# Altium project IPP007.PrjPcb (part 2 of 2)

## Sheet IPP007_SupportTop.SchDoc
size 431 x 279 mm; Date: Not shown in title block; ApprovedBy: Not shown in title block; CheckedBy: Not shown in title block; Author: Not shown in title block; CompanyName: Not shown in title block; Engineer: Not shown in title block; Organization: Not shown in title block; Address1: Not shown in title block; Address2: Not shown in title block; Address3: Not shown in title block; Address4: Not shown in title block; DocumentNumber: 10; Revision: Use project parameter SCH_Rev; SheetNumber: 10; SheetTotal: 14; PageSetup: Record=PageOptions¦CenterHorizontal=True¦CenterVertical=True¦PrintScale=1.00¦XCorrection=1.00¦YCorrection=1.00¦PrintKind=0¦BorderSize=5000000¦LeftOffset=0¦BottomOffset=0¦Orientation=2¦PaperLength=1000¦PaperWidth=1000¦Scale=100¦PaperSource=15¦PrintQuality=600¦MediaType=1¦DitherType=10¦PaperKind=Letter¦PrintScaleMode=1
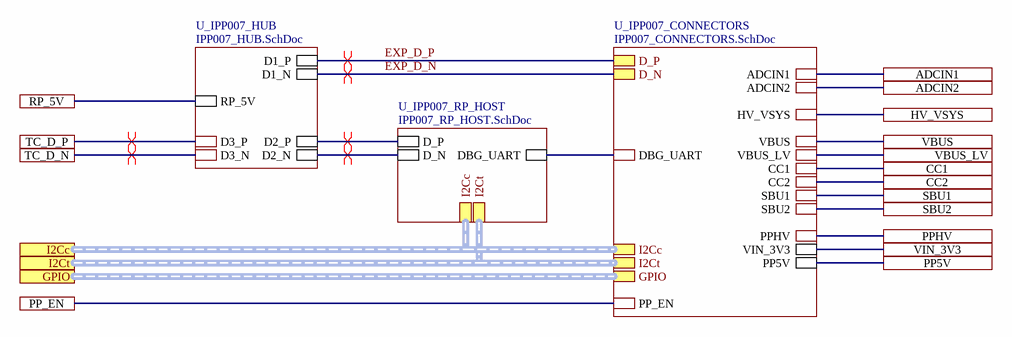
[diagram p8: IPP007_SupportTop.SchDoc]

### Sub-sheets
U_IPP007_CONNECTORS = IPP007_CONNECTORS.SchDoc: CC1, CC2, ADCIN1, ADCIN2, HV_VSYS, PPHV, PP5V, VIN_3V3, D_P, D_N, VBUS, VBUS_LV, DBG_UART, PP_EN, SBU2, SBU1, I2Cc (harness I2C), I2Ct (harness I2C), GPIO (harness GPIO)
U_IPP007_HUB = IPP007_HUB.SchDoc: D1_P, D1_N, D2_P, D2_N, RP_5V, D3_P, D3_N
U_IPP007_RP_HOST = IPP007_RP_HOST.SchDoc: DBG_UART, D_P, D_N, I2Cc (harness I2C), I2Ct (harness I2C)

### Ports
ADCIN1, ADCIN2, CC1, CC2, GPIO (harness GPIO), HV_VSYS, I2Cc (harness I2C), I2Ct (harness I2C), PP5V, PP_EN, PPHV, RP_5V, SBU1, SBU2, TC_D_N, TC_D_P, VBUS, VBUS_LV, VIN_3V3

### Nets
ADCIN1: port ADCIN1, sheet U_IPP007_CONNECTORS/ADCIN1
ADCIN2: port ADCIN2, sheet U_IPP007_CONNECTORS/ADCIN2
CC1: port CC1, sheet U_IPP007_CONNECTORS/CC1
CC2: port CC2, sheet U_IPP007_CONNECTORS/CC2
D2_N: sheet U_IPP007_RP_HOST/D_N, sheet U_IPP007_HUB/D2_N
D2_P: sheet U_IPP007_RP_HOST/D_P, sheet U_IPP007_HUB/D2_P
D3_N: port TC_D_N, sheet U_IPP007_HUB/D3_N
D3_P: port TC_D_P, sheet U_IPP007_HUB/D3_P
DBG_UART: sheet U_IPP007_CONNECTORS/DBG_UART, sheet U_IPP007_RP_HOST/DBG_UART
EXP_D_N: sheet U_IPP007_CONNECTORS/D_N, sheet U_IPP007_HUB/D1_N
EXP_D_P: sheet U_IPP007_CONNECTORS/D_P, sheet U_IPP007_HUB/D1_P
HV_VSYS: port HV_VSYS, sheet U_IPP007_CONNECTORS/HV_VSYS
PP5V: port PP5V, sheet U_IPP007_CONNECTORS/PP5V
PP_EN: port PP_EN, sheet U_IPP007_CONNECTORS/PP_EN
PPHV: port PPHV, sheet U_IPP007_CONNECTORS/PPHV
RP_5V: port RP_5V, sheet U_IPP007_HUB/RP_5V
SBU1: port SBU1, sheet U_IPP007_CONNECTORS/SBU1
SBU2: port SBU2, sheet U_IPP007_CONNECTORS/SBU2
VBUS: port VBUS, sheet U_IPP007_CONNECTORS/VBUS
VBUS_LV: port VBUS_LV, sheet U_IPP007_CONNECTORS/VBUS_LV
VIN_3V3: port VIN_3V3, sheet U_IPP007_CONNECTORS/VIN_3V3

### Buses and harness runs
harness port GPIO = sheet U_IPP007_CONNECTORS/GPIO
harness port I2Cc = sheet U_IPP007_CONNECTORS/I2Cc = sheet U_IPP007_RP_HOST/I2Cc
harness port I2Ct = sheet U_IPP007_CONNECTORS/I2Ct = sheet U_IPP007_RP_HOST/I2Ct

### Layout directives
differential pair: D2_N, D2_P, D3_N, D3_P, EXP_D_N, EXP_D_P

## Sheet IPP007_CONNECTORS.SchDoc
size 558 x 431 mm; Date: Not shown in title block; ApprovedBy: Not shown in title block; CheckedBy: Not shown in title block; Author: Not shown in title block; CompanyName: Not shown in title block; Engineer: Not shown in title block; Organization: Not shown in title block; Address1: Not shown in title block; Address2: Not shown in title block; Address3: Not shown in title block; Address4: Not shown in title block; DocumentNumber: 11; Revision: Use project parameter SCH_Rev; SheetNumber: 11; SheetTotal: 14; PageSetup: Record=PageOptions¦CenterHorizontal=True¦CenterVertical=True¦PrintScale=1.00¦XCorrection=1.00¦YCorrection=1.00¦PrintKind=0¦BorderSize=5000000¦LeftOffset=0¦BottomOffset=0¦Orientation=2¦PaperLength=1000¦PaperWidth=1000¦Scale=100¦PaperSource=15¦PrintQuality=600¦MediaType=1¦DitherType=10¦PaperKind=Letter¦PrintScaleMode=1
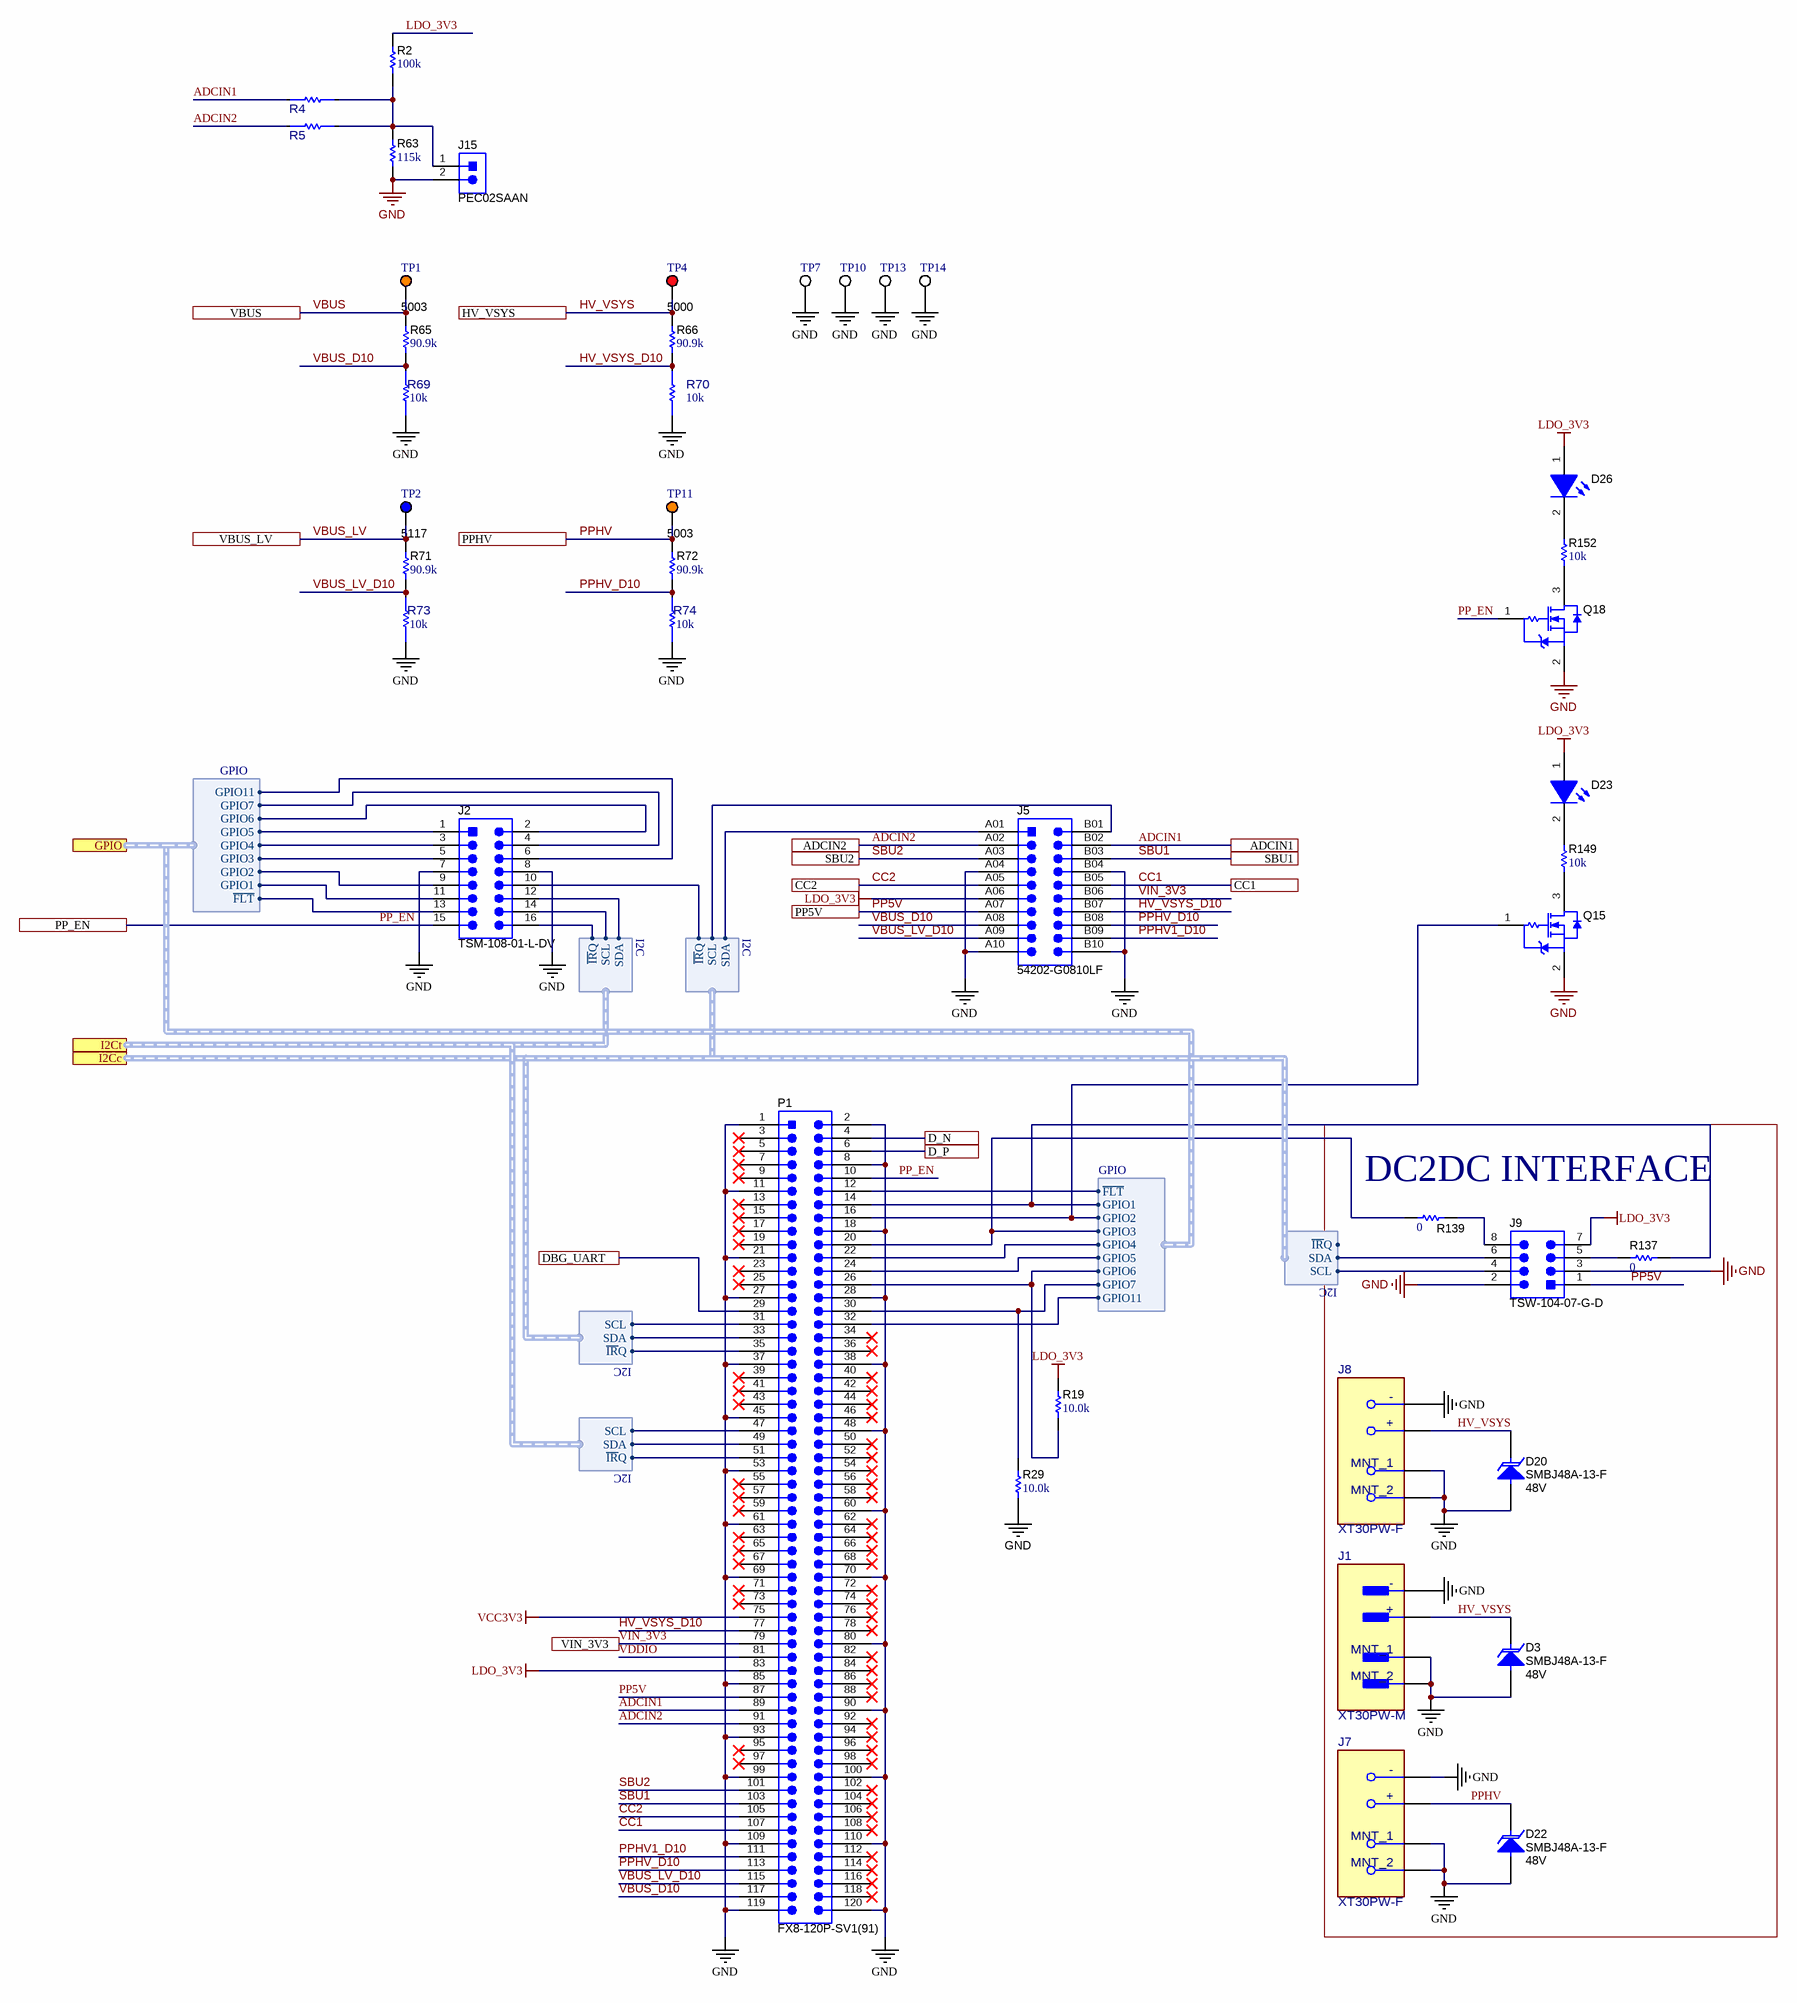
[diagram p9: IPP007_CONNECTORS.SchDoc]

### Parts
D3  SMBJ48A-13-F  value 48V  [SMB]
D20  SMBJ48A-13-F  value 48V  [SMB]
D22  SMBJ48A-13-F  value 48V  [SMB]
D23  LW QH8G-Q2S2-3K5L-1  [LW QH8G_White]  (value not drawn)
D26  LW QH8G-Q2S2-3K5L-1  [LW QH8G_White]  (value not drawn)
J1  XT30PW-M  [FP-XT30PW-M_CONN_PLUG2-MFG]
J2  TSM-108-01-L-DV  [Samtec_TSM-108-01-x-DV]
J5  54202-G0810LF  [FCI_54202-G0810LF]
J7  XT30PW-F  [FP-XT30PW-F_CONN_SOCKET_DC2-MFG]
J8  XT30PW-F  [FP-XT30PW-F_CONN_SOCKET_DC2-MFG]
J9  TSW-104-07-G-D  [TSW-104-07-G-D]
J15  PEC02SAAN  [CONN_PEC02SAAN]
P1  FX8-120P-SV1(91)  [Hirose_FX8-120P-SV1]
Q15  CSD15380F3  [YJM0003A]  (value not drawn)
Q18  CSD15380F3  [YJM0003A]  (value not drawn)
R2  ValueDisplayed: 100k  [0402L]  (hidden comment: ERJ-2RKF1003X)
R4  ERJ-H3G0R00V  [FP-ERJ-H3G0R00V_0603-MFG]  (value not drawn)
R5  ERJ-H3G0R00V  [FP-ERJ-H3G0R00V_0603-MFG]  (value not drawn)
R19  ValueDisplayed: 10.0k  [0201L]  (hidden comment: CRCW020110K0FKED)
R29  ValueDisplayed: 10.0k  [0201L]  (hidden comment: CRCW020110K0FKED)
R63  ValueDisplayed: 115k  [0402L]  (hidden comment: RC0402FR-07115KL)
R65  ValueDisplayed: 90.9k  [0402L]  (hidden comment: CRCW040290K9FKED)
R66  ValueDisplayed: 90.9k  [0402L]  (hidden comment: CRCW040290K9FKED)
R69  value 10k  [FP-CRCW040210K0FKEDC_0402-MFG]  (hidden comment: CRCW040210K0FKEDC)
R70  value 10k  [FP-CRCW040210K0FKEDC_0402-MFG]  (hidden comment: CRCW040210K0FKEDC)
R71  ValueDisplayed: 90.9k  [0402L]  (hidden comment: CRCW040290K9FKED)
R72  ValueDisplayed: 90.9k  [0402L]  (hidden comment: CRCW040290K9FKED)
R73  value 10k  [FP-CRCW040210K0FKEDC_0402-MFG]  (hidden comment: CRCW040210K0FKEDC)
R74  value 10k  [FP-CRCW040210K0FKEDC_0402-MFG]  (hidden comment: CRCW040210K0FKEDC)
R137  ValueDisplayed: 0  [0201L]  (hidden comment: CRCW02010000Z0ED)
R139  ValueDisplayed: 0  [0201L]  (hidden comment: CRCW02010000Z0ED)
R149  ValueDisplayed: 10k  [0402L]  (hidden comment: CRCW040210K0JNED)
R152  ValueDisplayed: 10k  [0402L]  (hidden comment: CRCW040210K0JNED)
TP1  5003  [Keystone5003]
TP2  5117  [Keystone5117]
TP4  5000  [Keystone5000]
TP7  5015  [Testpoint_Keystone_Miniature]  (value not drawn)
TP10  5015  [Testpoint_Keystone_Miniature]  (value not drawn)
TP11  5003  [Keystone5003]
TP13  5015  [Testpoint_Keystone_Miniature]  (value not drawn)
TP14  5015  [Testpoint_Keystone_Miniature]  (value not drawn)

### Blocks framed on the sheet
DC2DC INTERFACE: D3 D20 D22 J1 J7-J9 R137 R139

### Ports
ADCIN1, ADCIN2, CC1, CC2, D_N, D_P, DBG_UART, GPIO (harness GPIO), HV_VSYS, I2Cc (harness I2C), I2Ct (harness I2C), PP5V, PP_EN, PPHV, SBU1, SBU2, VBUS, VBUS_LV, VIN_3V3

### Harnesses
I2C: SCL, SDA, ~{IR}Q
GPIO: GPIO11, ~{FLT}, GPIO1, GPIO2, GPIO3, GPIO4, GPIO5, GPIO6, GPIO7

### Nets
GND: D3.2(A) D20.2(A) D22.2(A) J1.1(-) J1.3(MNT_1) J1.4(MNT_2) J2.7 J2.8 J5.A04 J5.A10 J5.B04 J5.B10 J7.1(-) J7.3(MNT_1) J7.4(MNT_2) J8.1(-) J8.3(MNT_1) J8.4(MNT_2) J9.2 J9.3 J15.2 P1.1 P1.2 P1.8 P1.11 P1.18 P1.21 P1.27 P1.28 P1.37 P1.38 P1.45 P1.48 P1.53 P1.60 P1.61 P1.69 P1.70 P1.80 P1.85 P1.90 P1.93 P1.99 P1.100 P1.109 P1.110 P1.119 P1.120 Q15.2(S) Q18.2(S) R29.1 R63.1 R69.1 R70.1 R73.1 R74.1 TP7.1 TP10.1 TP13.1 TP14.1
LDO_3V3: D23.1(A) D26.1(A) J5.A06 J9.7 P1.83 R2.2 R19.2
VCC3V3: P1.75
ADCIN1: J5.B02 P1.89 R4.1 ; port ADCIN1
ADCIN2: J5.A02 P1.91 R5.1 ; port ADCIN2
CC1: J5.B05 P1.107 ; port CC1
CC2: J5.A05 P1.105 ; port CC2
DBG_UART: P1.29 ; port DBG_UART
EXP_D_N: P1.4 ; port D_N
EXP_D_P: P1.6 ; port D_P
GPIO4: J2.3 P1.22 ; port GPIO.GPIO4
GPIO5: J2.1 P1.24 ; port GPIO.GPIO5
GPIO6: J2.2 P1.26 R19.1 ; port GPIO.GPIO6
GPIO7: J2.4 P1.30 R29.2 ; port GPIO.GPIO7
HV_VSYS: D3.1(K) D20.1(K) J1.2(+) J8.2(+) R66.2 TP4.1 ; port HV_VSYS
HV_VSYS_D10: J5.B07 P1.77 R66.1 R70.2
I2Cc_SCL: J5.B01 J9.4 P1.31 ; port I2Cc.SCL
I2Cc_SDA: J5.A01 J9.6 P1.33 ; port I2Cc.SDA
I2Ct_SCL: J2.14 P1.47 ; port I2Ct.SCL
I2Ct_SDA: J2.12 P1.49 ; port I2Ct.SDA
~{I2Cc_IRQ}: J2.10 P1.35 ; port I2Cc.~{IR}Q
~{I2Ct_IRQ}: J2.16 P1.51 ; port I2Ct.~{IR}Q
PP5V: J5.A07 J9.1 P1.87 ; port PP5V
PP_EN: J2.15 P1.10 Q18.1(G) ; port PP_EN
PPHV: D22.1(K) J7.2(+) R72.2 TP11.1 ; port PPHV
PPHV1_D10: J5.B09 P1.111
PPHV_D10: J5.B08 P1.113 R72.1 R74.2
SBU1: J5.B03 P1.103 ; port SBU1
SBU2: J5.A03 P1.101 ; port SBU2
VBUS: R65.2 TP1.1 ; port VBUS
VBUS_D10: J5.A08 P1.117 R65.1 R69.2
VBUS_LV: R71.2 TP2.1 ; port VBUS_LV
VBUS_LV_D10: J5.A09 P1.115 R71.1 R73.2
VDDIO: P1.81
VIN_3V3: J5.B06 P1.79 ; port VIN_3V3
NetD23_2: D23.2(K) R149.2
NetD26_2: D26.2(K) R152.2
NetJ2_5: J2.5 P1.20 R139.1 ; port GPIO.GPIO3
NetJ2_6: J2.6 P1.32 ; port GPIO.GPIO11
NetJ2_9: J2.9 P1.16 Q15.1(G) ; port GPIO.GPIO2
NetJ2_11: J2.11 P1.14 R137.1 ; port GPIO.GPIO1
NetJ2_13: J2.13 P1.12 ; port GPIO.~{FLT}
NetJ9_5: J9.5 R137.2
NetJ9_8: J9.8 R139.2
NetJ15_1: J15.1 R2.1 R4.2 R5.2 R63.2
NetQ15_3: Q15.3(D) R149.1
NetQ18_3: Q18.3(D) R152.1

Not connected (* = marked no-connect by the designer): P1 3* 5* 7* 9* 13* 15* 17* 19* 23* 25* 34* 36* 39* 40* 41* 42* 43* 44* 46* 50* 52* 54* 55* 56* 57* 58* 59* 62* 63* 64* 65* 66* 67* 68* 71* 72* 73* 74* 76* 78* 82* 84* 86* 88* 92* 94* 95* 96* 97* 98* 102* 104* 106* 108* 112* 114* 116* 118*

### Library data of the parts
D3 D20 D22 = CMP-0005570-3: Diode, TVS, Uni, 48 V, 77.4 Vc, SMB; Manufacturer: Diodes Inc.; Vbr_Min: 53.3V; AEC Category: Q101; Vbr_Max: 61.3V; Ppk: 600W; SizeZ_mm: 2.6; Ipp: 7.7A; SizeY_mm: 3.81; Vc: 77.4V; SizeAreaWB_mm2: 44.156; SizeX_mm: 5.6; SizeArea_mm2: 21.336
D23 D26 = CMP-0002919-2: LED, White, SMD; Manufacturer: OSRAM; Io_A: 5mA; Vr_V: 5V; Tjmax_C: 95°C; Value1: W; Angle: 120; Ir_A: 10nA; Vf_V: 2.8V
J1 = CMP-0121007-1: Socket, DC supply, XT30, male, PIN: 2, on PCBs, THT, yellow, 15A, 500V; Manufacturer: Amass; ContactFinish: Gold; AEC Qualified: No; Conn Orientation: Right Angle; DUT-Pitch_mm: 5mm; SizeZ_mm: 5.1mm; Standoff Height: 0.1mm
J2 = CMP-0075595-1: Header, 2.54mm, 8x2, Gold, SMT; Manufacturer: Samtec; Pitch_mm: 2.54; Gender: Male; Cert_CSA: Y; Current_A: 4.9A; Voltage_V: 475V; CT: False; Shrouded: N; Row_Count: 2; CNHeader: True
J5 = CMP-0077452-1: Header, 2.54mm, 10x2, Tin, SMT; Manufacturer: FCI; Pitch_mm: 2.54; Gender: Male; Cert_UL: Y; Voltage_V: 1.5kV; Shrouded: N; RowSpacing_mm: 5.46; Row_Count: 2
J7 J8 = CMP-0035193-3: Socket, DC supply, XT30, female, PIN: 2, on PCBs, THT, yellow, 15A; Manufacturer: Amass; ContactFinish: Gold; Voltage_V: 500V; AEC Qualified: No; Conn Orientation: Right Angle; DUT-Pitch_mm: 5mm; Is Female: yes; Standoff Height: 0.1mm
J9 = CMP-0075408-3: Header, 100mil, 4x2, Gold, TH; Manufacturer: Samtec; Gender: Male; Row_Count: 2; Cert_CSA: Y; Pitch_mm: 2.54; Green_REACh: Passed; Voltage_V: 550V; Current_A: 6.3A; Green_Lifecycle: Active; Cert_CULUS: N
J15 = CMP-0002337-1: Header, 100mil, 2x1, Tin, TH; Manufacturer: Sullins Connector Solutions; CNHeader: TRUE; Current_A: 3A; Green_Lifecycle: Not Set; Shrouded: N; Gender: Male; Green_REACh: Incomplete; Voltage_V: 1.8kV; Row_Count: 1; Pitch_mm: 2.54; CT: FALSE; Cert_UL: Y
P1 = CMP-0055794-1: Header(shrouded), 0.6mm, 60x2, Gold, SMT; Manufacturer: Hirose Electric Co. Ltd.; CNHeader: FALSE; Current_A: 400mA; Shrouded: Y; Gender: Male; Voltage_V: 100V; Row_Count: 2; Pitch_mm: 0.6
Q15 Q18 = CMP-0000206-2: MOSFET, N-CH, 20 V, 0.5 A, YJM0003A (PICOSTAR-3); Alternate Manufacturer: None; Manufacturer: Texas Instruments; SizeZ_mm: 0.35; ChType: N; Value2: 0.216 nC; Value1: 1.4; VdsMax_V: 20V; SizeX_mm: 0.69; SizeY_mm: 0.6; Vgs_V: 10V; Value: 20V; Rdson45_ohm: 1.46; SizeArea_mm2: 0.414; AEC Category: Q101; IdsMax_A: 500mA; SizeAreaWB_mm2: 2.704; U/M: EA; QgTyp_nC: 0.216
R2 = CMP-0026659-2: RES, 100 k, 1%, 0.1 W, 0402; Manufacturer: Panasonic; U/M: EA; Value2: 0.1W; EIA_Code: E96; Value: 100k; SizeArea_mm2: 0.5; TempCo: 100 ppm/C; SizeZ_mm: 0.6; AEC Category: Q200; VDC_V: 50V; Power_W: 100mW; AEC Grade: 0; SizeX_mm: 1; AEC Qualified: Yes
R4 R5 = CMP-0097467-1: 0 Ohms Jumper 0.125W, 1/8W Chip Resistor 0603 (1608 Metric) Automotive AEC-Q200 Thick Film; Manufacturer: Panasonic; Res_ohm: 0; VDC_V: 75V; Power_W: 125mW; AEC Qualified: Yes; Value: 0; SizeZ_mm: 0.55mm; AEC Grade: Grade 0
R19 R29 = CMP-0027262-3: RES, 10.0 k, 1%, 0.05 W, 0201; Manufacturer: Vishay-Dale; Power_W: 50mW; TempCo: 100 ppm/C; Value_Code: 10k0; Value: 10.0k; EIA_Code: E96; Res_ohm: 10k; SizeX_mm: 0.6; SizeY_mm: 0.3; SizeZ_mm: 0.26; Value2: 0.05W; SizeArea_mm2: 0.18; AEC Qualified: N; VDC_V: 30V; AEC Category: Q200
R63 = CMP-0077551-1: RES, 115 k, 1%, 0.063 W, 0402; Manufacturer: Yageo America; SizeArea_mm2: 0.5; AEC Qualified: N; AEC Category: Q200; Value: 115k; SizeZ_mm: 0.6; EIA_Code: E96; TempCo: 100 ppm/C; Power_W: 63mW; VDC_V: 50V; Value2: 0.063W; U/M: EA; SizeX_mm: 1.0
R65 R66 R71 R72 = CMP-0026605-2: RES, 90.9 k, 1%, 0.063 W, AEC-Q200 Grade 0, 0402; Manufacturer: Vishay-Dale; Power_W: 63mW; TempCo: 100 ppm/C; Value_Code: 90k9; Value: 90.9k; EIA_Code: E96; SizeX_mm: 1; SizeY_mm: 0.5; SizeZ_mm: 0.6; Value2: 0.063W; AEC Qualified: Y; VDC_V: 50V; AEC Category: Q200; AEC Grade: 0
R69 R70 R73 R74 = CMP-0094735-1: 10 kOhms ±1% 0.063W, 1/16W Chip Resistor 0402 (1005 Metric)  Thick Film; Manufacturer: Vishay; VDC_V: 50V; Power_W: 63mW; AEC Qualified: Yes; SizeZ_mm: 0.4mm; TempCo: 100ppm/°C; AEC Grade: Grade 0
R137 R139 = CMP-0027008-4: RES, 0, 5%, 0.05 W, 0201; Manufacturer: Vishay-Dale; Power_W: 50mW; TempCo: ppm/C; Value_Code: 0000; Value: 0; EIA_Code: E24; SizeX_mm: 0.6; SizeY_mm: 0.3; SizeZ_mm: 0.26; Value2: 0.05W; SizeArea_mm2: 0.18; AEC Qualified: N; AEC Category: Q200
R149 R152 = CMP-0026825-5: RES, 10 k, 5%, 0.063 W, AEC-Q200 Grade 0, 0402; Manufacturer: Vishay-Dale; Power_W: 63mW; TempCo: 200 ppm/C; Value_Code: 10k0; Value: 10k; EIA_Code: E24; SizeX_mm: 1; SizeY_mm: 0.5; SizeZ_mm: 0.6; Value2: 0.063W; AEC Qualified: Y; VDC_V: 50V; AEC Category: Q200; AEC Grade: 0
TP1 TP11 = CMP-0055140-2: Test Point, Miniature, Orange, TH; Manufacturer: Keystone Electronics; Green_Lifecycle: Active; ContactFinish: Silver; CNHeader: FALSE; CT: TRUE; Green_REACh: Passed
TP2 = CMP-0055154-1: Test Point, Miniature, Blue, TH; Manufacturer: Keystone; CNHeader: FALSE; Green_Lifecycle: Active; Green_REACh: Passed; ContactFinish: Silver; CT: TRUE
TP4 = CMP-0055137-2: Test Point, Miniature, Red, TH; Manufacturer: Keystone Electronics; Green_REACh: Passed; Green_Lifecycle: Active; ContactFinish: Silver; CNHeader: FALSE; CT: TRUE
TP7 TP10 TP13 TP14 = CMP-0055152-2: Test Point, Miniature, SMT; Manufacturer: Keystone Electronics; CNHeader: FALSE; Green_Lifecycle: Active; Green_REACh: Passed; CT: TRUE

## Sheet IPP007_RP_HOST.SchDoc
size 431 x 279 mm; Date: Not shown in title block; ApprovedBy: Not shown in title block; CheckedBy: Not shown in title block; Author: Not shown in title block; CompanyName: Not shown in title block; Engineer: Not shown in title block; Organization: Not shown in title block; Address1: Not shown in title block; Address2: Not shown in title block; Address3: Not shown in title block; Address4: Not shown in title block; DocumentNumber: 12; Revision: Use project parameter SCH_Rev; SheetNumber: 12; SheetTotal: 14; PageSetup: Record=PageOptions¦CenterHorizontal=True¦CenterVertical=True¦PrintScale=1.00¦XCorrection=1.00¦YCorrection=1.00¦PrintKind=0¦BorderSize=5000000¦LeftOffset=0¦BottomOffset=0¦Orientation=2¦PaperLength=1000¦PaperWidth=1000¦Scale=100¦PaperSource=15¦PrintQuality=600¦MediaType=1¦DitherType=10¦PaperKind=Letter¦PrintScaleMode=1
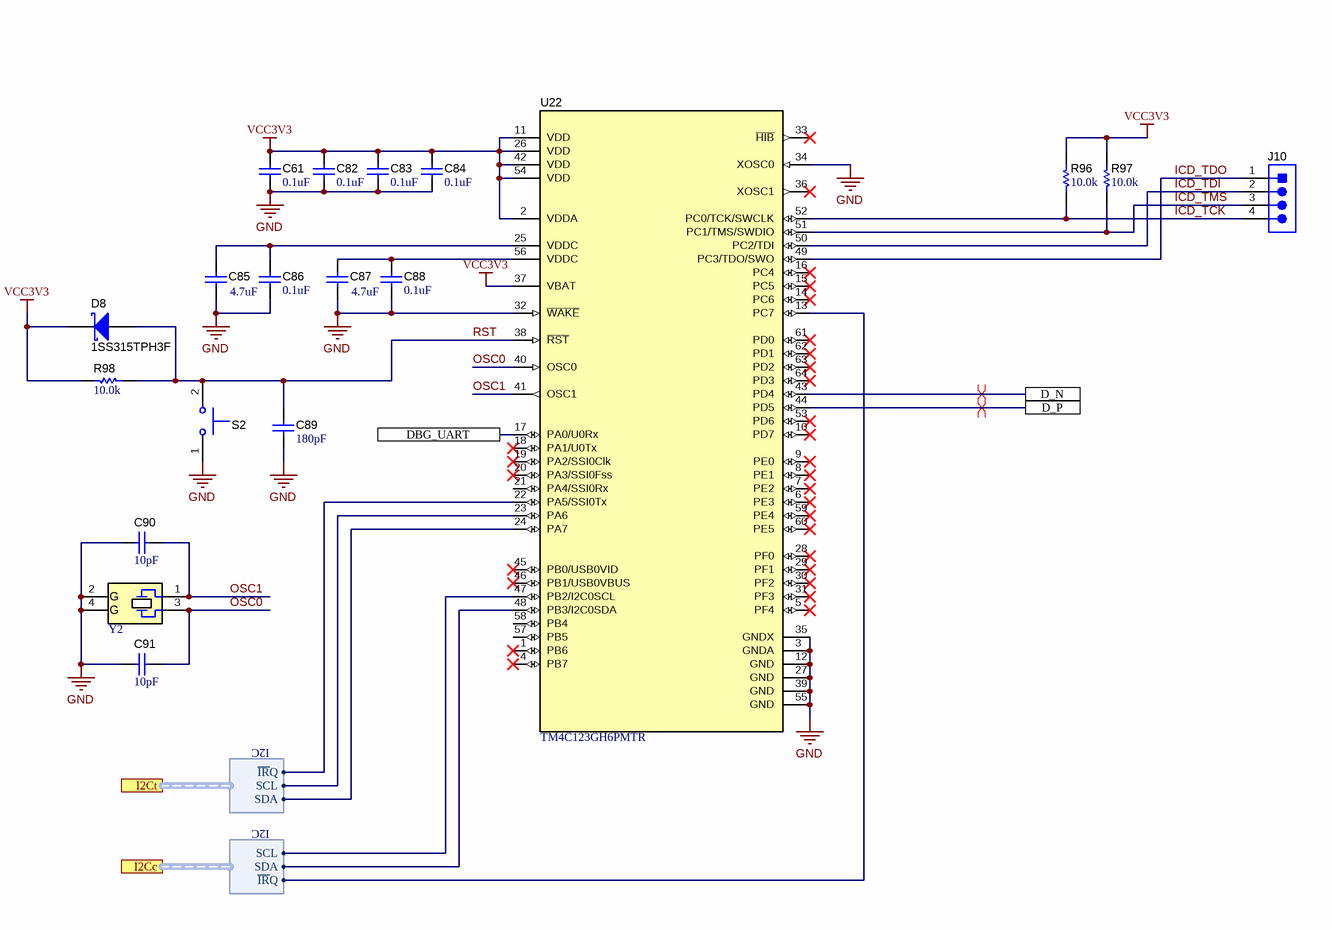
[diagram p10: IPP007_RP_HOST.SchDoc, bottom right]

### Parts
C61  ValueDisplayed: 0.1uF  [0402L]  (hidden comment: CGA2B3X7R1H104K050BB)
C82  ValueDisplayed: 0.1uF  [0402L]  (hidden comment: CGA2B3X7R1H104K050BB)
C83  ValueDisplayed: 0.1uF  [0402L]  (hidden comment: CGA2B3X7R1H104K050BB)
C84  ValueDisplayed: 0.1uF  [0402L]  (hidden comment: CGA2B3X7R1H104K050BB)
C85  ValueDisplayed: 4.7uF  [0402L]  (hidden comment: C1005X5R1A475M050BC)
C86  ValueDisplayed: 0.1uF  [0402L]  (hidden comment: CGA2B3X7R1H104K050BB)
C87  ValueDisplayed: 4.7uF  [0402L]  (hidden comment: C1005X5R1A475M050BC)
C88  ValueDisplayed: 0.1uF  [0402L]  (hidden comment: CGA2B3X7R1H104K050BB)
C89  ValueDisplayed: 180pF  [0603L]  (hidden comment: 06035A181JAT2A)
C90  ValueDisplayed: 10pF  [0603L]  (hidden comment: 06035A100JAT2A)
C91  ValueDisplayed: 10pF  [0603L]  (hidden comment: 06035A100JAT2A)
D8  1SS315TPH3F  [SOD-323]
J10  61300411121  [WURTH_61300411121]  (value not drawn)
R96  ValueDisplayed: 10.0k  [0402L]  (hidden comment: CRCW040210K0FKED)
R97  ValueDisplayed: 10.0k  [0402L]  (hidden comment: CRCW040210K0FKED)
R98  ValueDisplayed: 10.0k  [0402L]  (hidden comment: CRCW040210K0FKED)
S2  B3U-1000P  [SW_B3U-1000P]  (value not drawn)
U22  TM4C123GH6PMTR  [PM0064A_L]
Y2  NX3225GA-16.000M-STD-CRG-1  [NDK_NX3225GA]  (value not drawn)

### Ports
D_N, D_P, DBG_UART, I2Cc (harness I2C), I2Ct (harness I2C)

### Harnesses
I2C: SCL, SDA, ~{IR}Q

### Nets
GND: C61.2 C82.2 C83.2 C84.2 C85.2 C86.2 C87.2 C88.2 C89.1 C90.2 C91.2 S2.1 U22.3(GNDA) U22.12(GND) U22.27(GND) U22.32(~{WAKE}) U22.34(XOSC0) U22.35(GNDX) U22.39(GND) U22.55(GND) Y2.2(GND) Y2.4(GND)
VCC3V3: C61.1 C82.1 C83.1 C84.1 D8.1(K) R96.2 R97.2 R98.1 U22.2(VDDA) U22.11(VDD) U22.26(VDD) U22.37(VBAT) U22.42(VDD) U22.54(VDD)
D2_N: U22.43(PD4) ; port D_N
D2_P: U22.44(PD5) ; port D_P
DBG_UART: U22.17(PA0/U0Rx) ; port DBG_UART
I2Cc_SCL: U22.47(PB2/I2C0SCL) ; port I2Cc.SCL
I2Cc_SDA: U22.48(PB3/I2C0SDA) ; port I2Cc.SDA
I2Ct_SCL: U22.23(PA6) ; port I2Ct.SCL
I2Ct_SDA: U22.24(PA7) ; port I2Ct.SDA
~{I2Cc_IRQ}: U22.13(PC7) ; port I2Cc.~{IR}Q
~{I2Ct_IRQ}: U22.22(PA5/SSI0Tx) ; port I2Ct.~{IR}Q
ICD_TCK: J10.4 R96.1 U22.52(PC0/TCK/SWCLK)
ICD_TDI: J10.2 U22.50(PC2/TDI)
ICD_TDO: J10.1 U22.49(PC3/TDO/SWO)
ICD_TMS: J10.3 R97.1 U22.51(PC1/TMS/SWDIO)
OSC0: C91.1 U22.40(OSC0) Y2.3
OSC1: C90.1 U22.41(OSC1) Y2.1
RST: C89.2 D8.2(A) R98.2 S2.2 U22.38(~{RST})
NetC85_1: C85.1 C86.1 U22.25(VDDC)
NetC87_1: C87.1 C88.1 U22.56(VDDC)

Not connected (* = marked no-connect by the designer): U22 1(PB6)* 4(PB7)* 5(PF4)* 6(PE3)* 7(PE2)* 8(PE1)* 9(PE0)* 10(PD7)* 14(PC6)* 15(PC5)* 16(PC4)* 18(PA1/U0Tx)* 19(PA2/SSI0Clk)* 20(PA3/SSI0Fss)* 21(PA4/SSI0Rx) 28(PF0)* 29(PF1)* 30(PF2)* 31(PF3)* 33(~{HIB})* 36(XOSC1)* 45(PB0/USB0VID)* 46(PB1/USB0VBUS)* 53(PD6)* 57(PB5) 58(PB4) 59(PE4)* 60(PE5)* 61(PD0)* 62(PD1)* 63(PD2)* 64(PD3)*

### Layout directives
differential pair: D2_N, D2_P

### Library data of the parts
C61 C82-C84 C86 C88 = CMP-0006325-2: CAP, CERM, 0.1 uF, 50 V, +/- 10%, X7R, AEC-Q200 Grade 1, 0402; Manufacturer: TDK; TaMin_C: -55°C; ESR_ohm: 39.064m; Polarized: N; SizeAreaWB_mm2: 3; Value1: 0.039064 ohm; U/M: EA; Value: 0.1uF; TaMax_C: 125°C; SizeZ_mm: 0.6; SizeX_mm: 1; SizeY_mm: 0.5; Cap_Case: 0402; Value2: 50V; AEC Qualified: Y; Cap_F: 100nF; IRMS_A: 814.669mA; AEC Category: Q200
C85 C87 = CMP-0006269-2: CAP, CERM, 4.7 uF, 10 V, +/- 20%, X5R, 0402; Manufacturer: TDK; TaMin_C: -55°C; Polarized: N; SizeAreaWB_mm2: 3; Value1: Unknown; U/M: EA; Value: 4.7uF; TaMax_C: 85°C; SizeZ_mm: 0.6; SizeX_mm: 1; SizeY_mm: 0.5; Cap_Case: 0402; Value2: 10V; Cap_F: 4.7µF; AEC Category: Q200
C89 = CMP-0006770-4: CAP, CERM, 180 pF, 50 V, +/- 5%, C0G/NP0, 0603; Manufacturer: AVX; TaMin_C: -55°C; ESR_ohm: 90m; Polarized: N; SizeAreaWB_mm2: 4.68; Value1: 0.09 ohm; U/M: EA; Value: 180pF; TaMax_C: 125°C; SizeZ_mm: 1; SizeX_mm: 1.6; SizeY_mm: 0.8; Cap_Case: 0603; Value2: 50V; SizeArea_mm2: 1.28; AEC Category: Q200
C90 C91 = CMP-0006761-4: CAP, CERM, 10 pF, 50 V, +/- 5%, C0G/NP0, 0603; Manufacturer: AVX; TaMin_C: -55°C; ESR_ohm: 0.403; Polarized: N; SizeAreaWB_mm2: 4.68; Value1: 0.403 ohm; U/M: EA; Value: 10pF; TaMax_C: 125°C; SizeZ_mm: 1; SizeX_mm: 1.6; SizeY_mm: 0.8; Cap_Case: 0603; Value2: 50V; SizeArea_mm2: 1.28; AEC Category: Q200
D8 = CMP-0076922-2: Diode, Schottky, 5 V, 0.03 A, SOD-323; Manufacturer: Toshiba; Vr_V: 5V; Value: 5V; Green_REACh: Incomplete; Value1: 0.03A; Value2: 0.38V; SizeArea_mm2: 3.645; Vf_V: 380mV; Io_A: 30mA; SizeAreaWB_mm2: 8.695; SizeX_mm: 2.7; SizeZ_mm: 1.0; TJmax_C: 125°C; AEC Category: Q101; SizeY_mm: 1.35; Green_Lifecycle: Not Set
J10 = CMP-0054798-2: Header, 2.54 mm, 4x1, Gold, TH; Manufacturer: Wurth Elektronik; Pitch_mm: 2.54; Gender: Male; Row_Count: 1; Cert_UL: Y; Shrouded: N
R96-R98 = CMP-0025958-3: RES, 10.0 k, 1%, 0.063 W, AEC-Q200 Grade 0, 0402; Manufacturer: Vishay-Dale; Power_W: 63mW; TempCo: 100 ppm/C; Value_Code: 10k0; Value: 10.0k; EIA_Code: E96; Res_ohm: 10k; SizeX_mm: 1; SizeY_mm: 0.5; SizeZ_mm: 0.6; Value2: 0.063W; AEC Qualified: Y; VDC_V: 50V; AEC Category: Q200; AEC Grade: 0
S2 = CMP-0002150-2: SWITCH TACTILE SPST-NO 0.05A 12V; Manufacturer: Omron Electronic Components; CurrentRating_mA: 50A; PositionCount: 1; SwitchFunction: Off-Mom
U22 = CMP-0029860-3: Tiva C Series Microcontroller, 256 KB Flash, 32 KB SRAM, 12 Bit, 12 Channels, -40 to 105 degC, 64-Pin LQFP (PM), Green (RoHS & no Sb/Br), Tape and Reel; Manufacturer: Texas Instruments; ADC Channels: 12; Prefix: Qualified Device; Data Memory: 32 KB; I2C: 2; Tiva Series: Connected MCUs; Max Speed: 80 MHz; UART: 4; ADC Resolution: 12 Bit; GPIOs: 43; Program Memory: 256 KB
Y2 = CMP-0004635-3: Crystal, 16 MHz, 8pF, SMD; Manufacturer: NDK; TaMax_C: 70°C; TaMin_C: -10°C; Frequency Stability: +/-30ppm; Frequency_Fixed: 16MHz

## Sheet IPP007_HUB.SchDoc
size 431 x 279 mm; Date: Not shown in title block; ApprovedBy: Not shown in title block; CheckedBy: Not shown in title block; Author: Not shown in title block; CompanyName: Not shown in title block; Engineer: Not shown in title block; Organization: Not shown in title block; Address1: Not shown in title block; Address2: Not shown in title block; Address3: Not shown in title block; Address4: Not shown in title block; DocumentNumber: 13; Revision: Use project parameter SCH_Rev; SheetNumber: 13; SheetTotal: 14; PageSetup: Record=PageOptions¦CenterHorizontal=True¦CenterVertical=True¦PrintScale=1.00¦XCorrection=1.00¦YCorrection=1.00¦PrintKind=0¦BorderSize=5000000¦LeftOffset=0¦BottomOffset=0¦Orientation=2¦PaperLength=1000¦PaperWidth=1000¦Scale=100¦PaperSource=15¦PrintQuality=600¦MediaType=1¦DitherType=10¦PaperKind=Letter¦PrintScaleMode=1
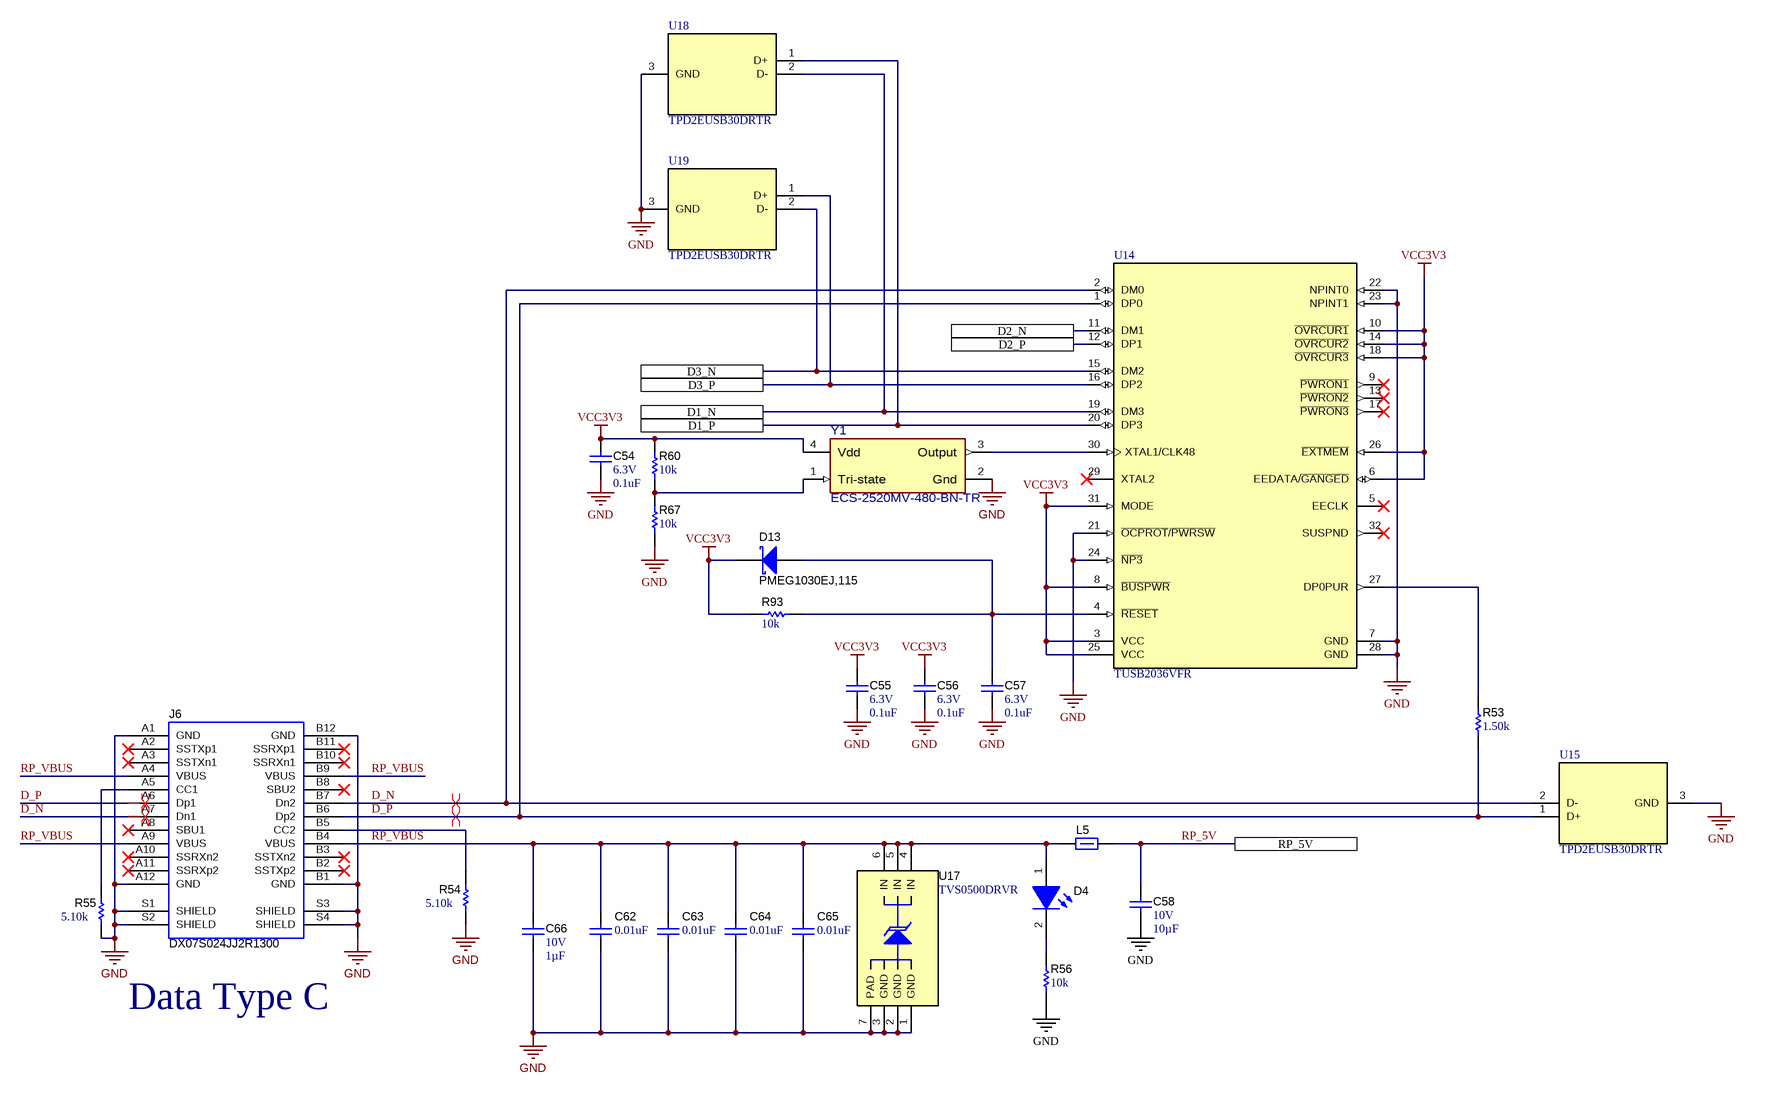
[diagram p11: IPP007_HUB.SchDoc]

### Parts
C54  VDC_V: 6.3V  ValueDisplayed: 0.1uF  [0402L]  (hidden comment: GRM155R60J104KA01D)
C55  VDC_V: 6.3V  ValueDisplayed: 0.1uF  [0402L]  (hidden comment: GRM155R60J104KA01D)
C56  VDC_V: 6.3V  ValueDisplayed: 0.1uF  [0402L]  (hidden comment: GRM155R60J104KA01D)
C57  VDC_V: 6.3V  ValueDisplayed: 0.1uF  [0402L]  (hidden comment: GRM155R60J104KA01D)
C58  VDC_V: 10V  ValueDisplayed: 10µF  [0402_080S]  (hidden comment: 0402ZD106MAT2A)
C62  ValueDisplayed: 0.01uF  [0402L]  (hidden comment: C0402C103J5RACTU)
C63  ValueDisplayed: 0.01uF  [0402L]  (hidden comment: C0402C103J5RACTU)
C64  ValueDisplayed: 0.01uF  [0402L]  (hidden comment: C0402C103J5RACTU)
C65  ValueDisplayed: 0.01uF  [0402L]  (hidden comment: C0402C103J5RACTU)
C66  VDC_V: 10V  ValueDisplayed: 1µF  [0402L]  (hidden comment: CC0402MRX5R6BB105)
D4  LW QH8G-Q2S2-3K5L-1  [LW QH8G_White]  (value not drawn)
D13  PMEG1030EJ,115  [SOD-323F]
J6  DX07S024JJ2R1300  [JAE_DX07S024JJ2R1300]
L5  742792021  [0805L]  (value not drawn)
R53  ValueDisplayed: 1.50k  [0402L]  (hidden comment: RMCF0402FT1K50)
R54  ValueDisplayed: 5.10k  [0201L]  (hidden comment: RC0201FR-075K1L)
R55  ValueDisplayed: 5.10k  [0201L]  (hidden comment: RC0201FR-075K1L)
R56  ValueDisplayed: 10k  [0402L]  (hidden comment: CRCW040210K0JNED)
R60  ValueDisplayed: 10k  [0402L]  (hidden comment: CRCW040210K0JNED)
R67  ValueDisplayed: 10k  [0402L]  (hidden comment: CRCW040210K0JNED)
R93  ValueDisplayed: 10k  [0402L]  (hidden comment: CRCW040210K0JNED)
U14  TUSB2036VFR  [VF0032A_L]
U15  TPD2EUSB30DRTR  [DRT0003A]
U17  TVS0500DRVR  [DRV0006A]
U18  TPD2EUSB30DRTR  [DRT0003A]
U19  TPD2EUSB30DRTR  [DRT0003A]
Y1  ECS-2520MV-480-BN-TR  [FP-ECS-2520MV-480-BN-TR_SMT_OSC_2MM5_2MM0-MFG]

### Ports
D1_N, D1_P, D2_N, D2_P, D3_N, D3_P, RP_5V

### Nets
GND: C54.2 C55.2 C56.2 C57.2 C58.2 C62.2 C63.2 C64.2 C65.2 C66.2 J6.A1(GND) J6.A12(GND) J6.B1(GND) J6.B12(GND) J6.S1(SHIELD) J6.S2(SHIELD) J6.S3(SHIELD) J6.S4(SHIELD) R54.2 R55.2 R56.1 R67.1 U14.7(GND) U14.21(~{OCPROT}/~{PWRSW}) U14.22(NPINT0) U14.23(NPINT1) U14.24(~{NP3}) U14.28(GND) U15.3(GND) U17.1(GND) U17.2(GND) U17.3(GND) U17.7(PAD) U18.3(GND) U19.3(GND) Y1.2(Gnd)
VCC3V3: C54.1 C55.1 C56.1 D13.1(K) R60.2 R93.2 U14.3(VCC) U14.6(EEDATA/~{GANGED}) U14.8(~{BUSPWR}) U14.10(~{OVRCUR1}) U14.14(~{OVRCUR2}) U14.18(~{OVRCUR3}) U14.25(VCC) U14.26(~{EXTMEM}) U14.31(MODE) Y1.4(Vdd)
D2_N: U14.11(DM1) ; port D2_N
D2_P: U14.12(DP1) ; port D2_P
D3_N: U14.15(DM2) U19.2(D-) ; port D3_N
D3_P: U14.16(DP2) U19.1(D+) ; port D3_P
D_N: J6.A7(Dn1) J6.B7(Dn2) U14.2(DM0) U15.2(D-)
D_P: J6.A6(Dp1) J6.B6(Dp2) R53.1 U14.1(DP0) U15.1(D+)
EXP_D_N: U14.19(DM3) U18.2(D-) ; port D1_N
EXP_D_P: U14.20(DP3) U18.1(D+) ; port D1_P
RP_5V: C58.1 L5.2 ; port RP_5V
RP_VBUS: C62.1 C63.1 C64.1 C65.1 C66.1 D4.1(A) J6.A4(VBUS) J6.A9(VBUS) J6.B4(VBUS) J6.B9(VBUS) L5.1 U17.4(IN) U17.5(IN) U17.6(IN)
NetC57_1: C57.1 D13.2(A) R93.1 U14.4(~{RESET})
NetD4_2: D4.2(K) R56.2
NetJ6_A5: J6.A5(CC1) R55.1
NetJ6_B5: J6.B5(CC2) R54.1
NetR53_2: R53.2 U14.27(DP0PUR)
NetR60_1: R60.1 R67.2 Y1.1(Tri-state)
NetU14_30: U14.30(XTAL1/CLK48) Y1.3(Output)

Not connected (* = marked no-connect by the designer): J6 A2(SSTXp1)* A3(SSTXn1)* A8(SBU1)* A10(SSRXn2)* A11(SSRXp2)* B2(SSTXp2)* B3(SSTXn2)* B8(SBU2)* B10(SSRXn1)* B11(SSRXp1)*; U14 5(EECLK)* 9(~{PWRON1})* 13(~{PWRON2})* 17(~{PWRON3})* 29(XTAL2)* 32(SUSPND)*

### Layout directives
differential pair: D_N, D_P

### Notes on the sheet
- Data Type C

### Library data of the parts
C54-C57 = CMP-0006531-2: CAP, CERM, 0.1 uF, 6.3 V, +/- 10%, X5R, 0402; Manufacturer: MuRata; TaMin_C: -55°C; Polarized: N; SizeAreaWB_mm2: 3; Value1: Unknown; U/M: EA; Value: 0.1uF; TaMax_C: 85°C; SizeZ_mm: 0.6; SizeX_mm: 1; SizeY_mm: 0.5; Cap_Case: 0402; Cap_F: 100nF; AEC Category: Q200
C58 = CMP-0078623-1: CAP, CERM, 10 µF, 10 V,+/- 20%, X5R, 0402; Manufacturer: AVX; SizeAreaWB_mm2: 3; SizeArea_mm2: 0.5; AEC Qualified: N; AEC Category: Q200; Value: 10uF; TaMax_C: 85°C; SizeZ_mm: 0.8; TaMin_C: -55°C; U/M: EA; SizeX_mm: 1; Cap_Case: 0402_080
C62-C65 = CMP-0006236-2: CAP, CERM, 0.01 uF, 50 V, +/- 5%, X7R, 0402; Manufacturer: Kemet; TaMin_C: -55°C; Polarized: N; SizeAreaWB_mm2: 3; Value1: Unknown; U/M: EA; Value: 0.01uF; TaMax_C: 125°C; SizeZ_mm: 0.6; SizeX_mm: 1; SizeY_mm: 0.5; Cap_Case: 0402; Value2: 50V; Cap_F: 10nF; AEC Category: Q200
C66 = CMP-0081457-1: CAP, CERM, 1 µF, 10 V,+/- 20%, X5R, 0402; Manufacturer: Yageo America; TaMin_C: -55°C; Polarized: N; SizeAreaWB_mm2: 3; U/M: EA; Value: 1uF; TaMax_C: 85°C; SizeZ_mm: 0.6; SizeX_mm: 1; SizeY_mm: 0.5; Cap_Case: 0402; AEC Category: Q200
D4 = CMP-0002919-2: as D23 on sheet IPP007_CONNECTORS
D13 = CMP-0028852-2: Diode, Schottky, 10 V, 3 A, SOD-323F; Manufacturer: Nexperia; SizeZ_mm: 0.8; Value1: 3A; AEC Category: Q101; Value: 10V; Green_REACh: Incomplete; SizeX_mm: 2.5; Green_Lifecycle: Not Set; SizeAreaWB_mm2: 7.875; AEC Qualified: N; Vf_V: 530mV; SizeArea_mm2: 3.125; Value2: 0.53V; SizeY_mm: 1.25; TJmax_C: 150°C
J6 = CMP-0085712-2: Receptacle, USB 3.1 Type C, R/A, Gold, SMT; Manufacturer: JAE Electronics; Current_A: 1.25A; Gender: Female; Voltage_V: 20V; Pitch_mm: 0.5; Row_Count: 2
L5 = CMP-0003072-1: Ferrite Bead, 22 ohm @ 100 MHz, 6 A, 0805; Manufacturer: Wurth Elektronik; Ztyp@1GHz_Ohm: 40.219; ZTyp@100MHz_Ohm: 22; SizeAreaWB_mm2: 6.75; DCR_ohm: 8m; Value1: 0.008 ohm; Value: 22 ohm; Imax_A: 6A; SizeZ_mm: 1.45; SizeX_mm: 2; SizeY_mm: 1.25; SizeArea_mm2: 2.5
R53 = CMP-0026756-1: RES, 1.50 k, 1%, 0.063 W, AEC-Q200 Grade 0, 0402; Manufacturer: Stackpole Electronics Inc; Power_W: 63mW; TempCo: 100 ppm/C; Value_Code: 1k50; U/M: EA; Value: 1.50k; EIA_Code: E96; Res_ohm: 1.5k; SizeX_mm: 1; SizeY_mm: 0.5; SizeZ_mm: 0.6; Value2: 0.063W; AEC Qualified: Y; VDC_V: 50V; AEC Grade: 0; AEC Category: Q200
R54 R55 = CMP-0027789-1: RES, 5.10 k, 1%, 0.05 W, 0201; Manufacturer: Yageo America; Power_W: 50mW; TempCo: 200 ppm/C; Value_Code: 5k10; U/M: EA; Value: 5.10k; Res_ohm: 5.1k; SizeX_mm: 0.6; SizeY_mm: 0.3; SizeZ_mm: 0.26; Value2: 0.05W; SizeArea_mm2: 0.18; AEC Qualified: N; VDC_V: 25V; AEC Category: Q200
R56 R60 R67 R93 = CMP-0026825-5: as R149 on sheet IPP007_CONNECTORS
U14 = CMP-0033740-1: 2 / 3-Port Hub for USB with Optional Serial EEPROM Interface, 3.3V, 0 to 70 degC, 32-Pin LQFP (VF), Green (RoHS & no Sb/Br); Manufacturer: Texas Instruments; USB Speed: Full; SubFamily: USB Hub Controller; USB Full Speed: True; Supply Voltage(s)(V): 3.3
U15 U18 U19 = CMP-0043104-2: ESD Solution for Super-Speed (6 Gbps) USB 3.0 Interface, 2 Channels, -40 to +85 degC, 3-pin SOT (DRT), Green (Rohs & No Sb/Br); Manufacturer: Texas Instruments; IO Leakage Current(nA): 10; HDMI: TRUE; IO Capacitance(Typ)(pF): 0.7; Breakdown Voltage(Min)(V): 9; Differential Capacitance(pF): 0.01; IEC 61000-4-2 Air-Gap(+/- kV): 8
U17 = CMP-0077837-1: 5-V Precision Surge Protection Clamp, DRV0006A (WSON-6); Alternate Manufacturer: Texas Instruments; SizeAreaWB_mm2: 9.0; SizeZ_mm: 0.8; SizeX_mm: 2.0; SizeArea_mm2: 4.0; CompType: IC; AEC Qualified: N; AEC Category: Q200
Y1 = CMP-0121117-1: Oscillator XO 48MHz ±50ppm 15pF HCMOS 55% 1.8V/2.5V/3.3V 4-Pin Mini-CSMD T/R; Manufacturer: ECS International; SizeZ_mm: 0.9mm; AEC Qualified: No; Max Supply Current: 8mA; Max Supply Voltage: 3.6V; Min Supply Voltage: 1.6V

## Sheet IPP007_BIDI_PP.SchDoc
size 431 x 279 mm; Date: Not shown in title block; ApprovedBy: Not shown in title block; CheckedBy: Not shown in title block; Author: Not shown in title block; CompanyName: Not shown in title block; Engineer: Not shown in title block; Organization: Not shown in title block; Address1: Not shown in title block; Address2: Not shown in title block; Address3: Not shown in title block; Address4: Not shown in title block; DocumentNumber: 6; Revision: Use project parameter SCH_Rev; SheetNumber: 6; SheetTotal: 14; PageSetup: Record=PageOptions¦CenterHorizontal=True¦CenterVertical=True¦PrintScale=0.97¦XCorrection=1.00¦YCorrection=1.00¦PrintKind=0¦BorderSize=5000000¦LeftOffset=0¦BottomOffset=0¦Orientation=2¦PaperLength=1000¦PaperWidth=1000¦Scale=100¦PaperSource=15¦PrintQuality=600¦MediaType=1¦DitherType=10¦PaperKind=Letter¦PrintScaleMode=1
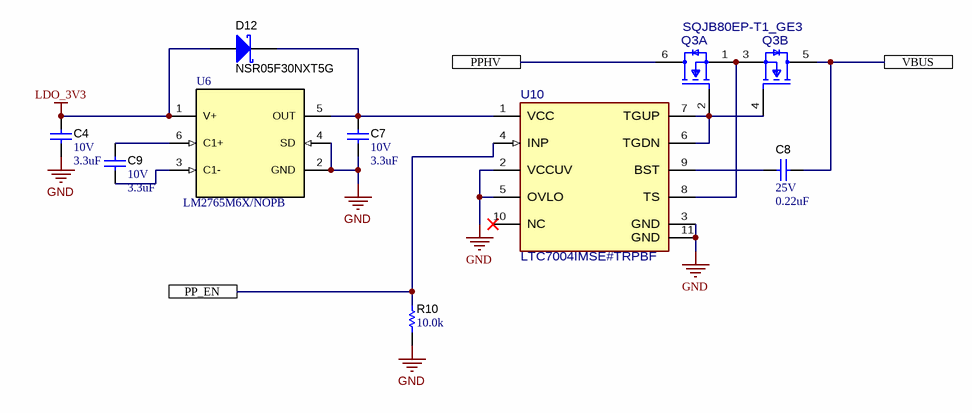
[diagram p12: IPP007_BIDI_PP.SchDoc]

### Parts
C4  VDC_V: 10V  ValueDisplayed: 3.3uF  [0402L]  (hidden comment: C1005X5R1A335K050BC)
C7  VDC_V: 10V  ValueDisplayed: 3.3uF  [0402L]  (hidden comment: C1005X5R1A335K050BC)
C8  VDC_V: 25V  ValueDisplayed: 0.22uF  [0402L]  (hidden comment: C1005X5R1E224M050BC)
C9  VDC_V: 10V  ValueDisplayed: 3.3uF  [0402L]  (hidden comment: C1005X5R1A335K050BC)
D12  NSR05F30NXT5G  [DSN2_0402]
Q3  SQJB80EP-T1_GE3  [FP-SQJB80EP-T1_GE3_SO-8L-DUAL-MFG]  (value not drawn)  (parts A,B of 2)
R10  ValueDisplayed: 10.0k  [0201L]  (hidden comment: RC0201FS-7D10KL)
U6  LM2765M6X/NOPB  [DBV0006A_N]
U10  LTC7004IMSE#TRPBF  [FP-LTC7004IMSE_TRPBF_MSOP10-MFG]

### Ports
PP_EN, PPHV, VBUS

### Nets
GND: C4.2 C7.1 R10.1 U6.2(GND) U6.4(SD) U10.2(VCCUV) U10.3(GND) U10.5(OVLO) U10.11(GND)
LDO_3V3: C4.1 D12.2(A) U6.1(V+)
PP_EN: R10.2 U10.4(INP) ; port PP_EN
PPHV: Q3.6(D1) ; port PPHV
VBUS: C8.1 Q3.5(D2) ; port VBUS
NetC7_2: C7.2 D12.1(K) U6.5(OUT) U10.1(VCC)
NetC8_2: C8.2 U10.9(BST)
NetC9_1: C9.1 U6.3(C1-)
NetC9_2: C9.2 U6.6(C1+)
NetQ3_1: Q3.1(S1) Q3.3(S2) U10.8(TS)
NetQ3_2: Q3.2(G1) Q3.4(G2) U10.6(TGDN) U10.7(TGUP)

Not connected (* = marked no-connect by the designer): U10 10(NC)*

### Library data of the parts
C4 C7 C9 = CMP-0006265-2: CAP, CERM, 3.3 uF, 10 V, +/- 10%, X5R, 0402; Manufacturer: TDK; TaMin_C: -55°C; ESR_ohm: 4.157m; Polarized: N; SizeAreaWB_mm2: 3; Value1: 0.004157 ohm; U/M: EA; Value: 3.3uF; TaMax_C: 85°C; SizeZ_mm: 0.6; SizeX_mm: 1; SizeY_mm: 0.5; Cap_Case: 0402; Cap_F: 3.3µF; IRMS_A: 2.4539A; AEC Category: Q200
C8 = CMP-0006277-2: CAP, CERM, 0.22 uF, 25 V, +/- 20%, X5R, 0402; Manufacturer: TDK; TaMin_C: -55°C; Polarized: N; SizeAreaWB_mm2: 3; Value1: Unknown; U/M: EA; Value: 0.22uF; TaMax_C: 85°C; SizeZ_mm: 0.6; SizeX_mm: 1; SizeY_mm: 0.5; Cap_Case: 0402; Cap_F: 220nF; AEC Category: Q200
D12 = CMP-0077002-2: Diode, Schottky, 30 V, 0.5 A, 0402 Diode; Manufacturer: ON Semiconductor; Green_REACh: Passed; Value: 30V; AEC Category: Q101; Io_A: 500mA; Vf_V: 430mV; SizeZ_mm: 0.31; SizeAreaWB_mm2: 3.2; TJmax_C: 150°C; Green_Lifecycle: Active; Value2: 0.43V; SizeX_mm: 1.0; SizeY_mm: 0.6; Value1: 0.5A
Q3 = CMP-0120201-1: Mosfet Array 80V 30A (Tc) 48W Surface Mount PowerPAK® SO-8 Dual; Manufacturer: Vishay; AEC Qualified: Yes; QgTyp_nC: 20nC @ 10V; Rdson45_ohm: 15.5m; SizeZ_mm: 1.267mm; VdsMax_V: 1.2V; Vgs_V: 20V; ChMode: False; AEC Grade: Grade 0; Input Capacitace At Vds: 1015pF @ 25V; Number Of Channels: 2; Pulse Drain Current: 84A; Reverse Recovery Charge: 43nC; Reverse Recovery Time: 37ns; Rthja Max: 85°C/W; Standoff Height: 0mm; Threshold Vgs Max: 2.5V; Threshold Vgs Min: 1.5V; TJmax_C: +175°C; Transconductance: 29S; Turn Off Delay Time: 23ns; Turn On Delay Time: 10ns; Typ Forward Diode Voltage: 0.84V
R10 = CMP-0028071-1: RES, 10.0 k, 1%, 0.05 W, 0201; Manufacturer: Yageo America; Power_W: 50mW; TempCo: 200 ppm/C; Value_Code: 10k0; U/M: EA; Value: 10.0k; EIA_Code: E96; Res_ohm: 10k; SizeX_mm: 0.6; SizeY_mm: 0.3; SizeZ_mm: 0.26; Value2: 0.05W; SizeArea_mm2: 0.18; AEC Qualified: N; VDC_V: 25V; AEC Category: Q200
U6 = CMP-0072086-1: Switched Capacitor Voltage Converter, 6-pin SOT-23, Pb-Free; Manufacturer: Texas Instruments; PackageTopMarking: S15B*XTT; CompType: Switch Caps; PowerWise: N
U10 = CMP-0120203-2: High-Side Gate Driver IC Non-Inverting 10-MSOP-EP; Manufacturer: Analog Devices; SizeZ_mm: 1.1mm; AEC Qualified: No; Fall Time: 13ns; Max Supply Voltage: 15V; Min Supply Voltage: 3.5V; Nominal Supply Current: 225uA; Number Of Drivers: 1; Standoff Height: 0.0508mm; TJmax_C: +125°C

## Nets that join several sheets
GND: IPP007_HARDWARE (H1.1 H2.1 H3.1 H4.1), TPS26750 (45 pins), MOISTURE_DETECT (QN1.2 QN2.2 R52.1), PP5V_SUPPLY (42 pins), IPP007_TC_POWER (41 pins), IPP007_CONNECTORS (60 pins), IPP007_RP_HOST (22 pins), IPP007_HUB (36 pins), IPP007_BIDI_PP (9 pins)
LDO_3V3: TPS26750 (17 pins), MOISTURE_DETECT (QP1.2 QP2.2 R47.2), IPP007_CONNECTORS (7 pins), IPP007_BIDI_PP (C4.1 D12.2 U6.1)
VCC3V3: PP5V_SUPPLY (C6.1 U3.1), IPP007_CONNECTORS (P1.75), IPP007_RP_HOST (14 pins), IPP007_HUB (16 pins)
ADCIN1: TPS26750 (R7.1 R9.2 U2.2), IPP007_CONNECTORS (J5.B02 P1.89 R4.1)
ADCIN2: TPS26750 (R6.1 R8.2 U2.3), IPP007_CONNECTORS (J5.A02 P1.91 R5.1)
CC1: TPS26750 (C52.1 U2.24 U12.12), IPP007_CONNECTORS (J5.B05 P1.107)
CC2: TPS26750 (C51.1 U2.25 U12.11), IPP007_CONNECTORS (J5.A05 P1.105)
D2_N: IPP007_RP_HOST (U22.43), IPP007_HUB (U14.11)
D2_P: IPP007_RP_HOST (U22.44), IPP007_HUB (U14.12)
D3_N: TPS26750 (R89.2), IPP007_HUB (U14.15 U19.2)
D3_P: TPS26750 (R90.2), IPP007_HUB (U14.16 U19.1)
DBG_UART: IPP007_CONNECTORS (P1.29), IPP007_RP_HOST (U22.17)
EXP_D_N: IPP007_CONNECTORS (P1.4), IPP007_HUB (U14.19 U18.2)
EXP_D_P: IPP007_CONNECTORS (P1.6), IPP007_HUB (U14.20 U18.1)
GPIO4: TPS26750 (R78.1 U2.22), MOISTURE_DETECT (R25.1), IPP007_CONNECTORS (J2.3 P1.22)
GPIO5: TPS26750 (R77.1 U2.23), MOISTURE_DETECT (R26.2), IPP007_CONNECTORS (J2.1 P1.24)
GPIO6: TPS26750 (U2.31), MOISTURE_DETECT (R24.1), IPP007_CONNECTORS (J2.2 P1.26 R19.1)
GPIO7: TPS26750 (U2.30), MOISTURE_DETECT (R30.1), IPP007_CONNECTORS (J2.4 P1.30 R29.2)
HV_VSYS: IPP007_SystemPower (D1.1), PP5V_SUPPLY (6 pins), IPP007_CONNECTORS (6 pins)
I2Cc_SCL: TPS26750 (R42.2 U2.16 U13.6), IPP007_CONNECTORS (J5.B01 J9.4 P1.31), IPP007_RP_HOST (U22.47)
I2Cc_SDA: TPS26750 (J14.2 R43.2 U2.15), IPP007_CONNECTORS (J5.A01 J9.6 P1.33), IPP007_RP_HOST (U22.48)
I2Ct_SCL: TPS26750 (R36.2 U2.9), IPP007_CONNECTORS (J2.14 P1.47), IPP007_RP_HOST (U22.23)
I2Ct_SDA: TPS26750 (R37.2 U2.8), IPP007_CONNECTORS (J2.12 P1.49), IPP007_RP_HOST (U22.24)
~{I2Cc_IRQ}: TPS26750 (R44.2 U2.17), IPP007_CONNECTORS (J2.10 P1.35), IPP007_RP_HOST (U22.13)
~{I2Ct_IRQ}: TPS26750 (R38.2 U2.10), IPP007_CONNECTORS (J2.16 P1.51), IPP007_RP_HOST (U22.22)
NetJ2_5: TPS26750 (U2.18), IPP007_CONNECTORS (J2.5 P1.20 R139.1)
NetJ2_6: TPS26750 (U2.13), IPP007_CONNECTORS (J2.6 P1.32)
NetJ2_9: TPS26750 (U2.7 U12.16), IPP007_CONNECTORS (J2.9 P1.16 Q15.1)
NetJ2_11: TPS26750 (U2.6), IPP007_CONNECTORS (J2.11 P1.14 R137.1)
NetJ2_13: TPS26750 (R31.2 U12.9), IPP007_CONNECTORS (J2.13 P1.12)
PP5V: TPS26750 (C43.1 C44.1 U2.28 U2.29), PP5V_SUPPLY (U4.6), IPP007_CONNECTORS (J5.A07 J9.1 P1.87)
PP_EN: TPS26750 (Q7.3 R35.1), IPP007_CONNECTORS (J2.15 P1.10 Q18.1), IPP007_BIDI_PP (R10.2 U10.4)
PPHV: PP5V_SUPPLY (C59.1 R1.2 U20.8), IPP007_CONNECTORS (D22.1 J7.2 R72.2 TP11.1), IPP007_BIDI_PP (Q3.6)
RP_5V: PP5V_SUPPLY (D10.2), IPP007_HUB (C58.1 L5.2)
SBU1: TPS26750 (U12.15), MOISTURE_DETECT (R27.1), IPP007_CONNECTORS (J5.B03 P1.103)
SBU2: TPS26750 (U12.14), MOISTURE_DETECT (R28.2), IPP007_CONNECTORS (J5.A03 P1.101)
TC_VSYS: IPP007_SystemPower (D1.2), IPP007_TC_POWER (10 pins)
VBUS: TPS26750 (9 pins), IPP007_CONNECTORS (R65.2 TP1.1), IPP007_BIDI_PP (C8.1 Q3.5)
VBUS_LV: TPS26750 (8 pins), IPP007_CONNECTORS (R71.2 TP2.1)
VIN_3V3: TPS26750 (C42.1 U2.32), PP5V_SUPPLY (C1.1 U1.1), IPP007_CONNECTORS (J5.B06 P1.79)

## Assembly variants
001: not fitted P1 R6 R7 R8 R9 R10 R19 R29 R67 R77 R78 R94 R95 R137 R139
